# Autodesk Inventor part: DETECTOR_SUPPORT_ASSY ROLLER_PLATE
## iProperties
Shininess: 64.0
Length Units: 11272
Angle Units: 11279
Time Units: 11290
Mass Units: 11286
Length Display Precision: 3
Angle Display Precision: 2
Compacted: True
Part Number: DETECTOR_SUPPORT_ASSY ROLLER_PLATE
Document SubType Name: Modeling
Created: 2004-08
Designer: John Blackburn
Material: MILD_STEEL
Manufacturer: Standard
Standards Organization: Custom
Density: 0.0
Volumn: 0.0
Area: 0.0
PropertySet Name: Model Information
Control State: 0
Master: False
Checked Out: False
Author: John Blackburn
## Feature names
1. ExtrusionMidplane1
2. ExtrusionMidplane2
3. ExtrusionThru1
4. AM_HOLE_SI0030_1 [Hole]
5. Rectangular Pattern1
